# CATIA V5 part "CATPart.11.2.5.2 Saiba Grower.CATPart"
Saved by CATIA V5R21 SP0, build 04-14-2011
Part number: Şaibă Grower (varianta N)
Bounding box of the stored display mesh (mm): x -3.747 to 3.719, y 0 to 1.5, z -3.701 to 3.685
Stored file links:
  C:\Users\MIRCEA\Desktop\MOM\Mogan\model\CATPart.11.2.5.2 Saiba Grower.CATPart
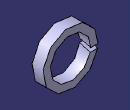
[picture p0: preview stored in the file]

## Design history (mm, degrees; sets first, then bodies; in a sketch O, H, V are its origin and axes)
Parameters
  d1 = 5.5 mm
  d2 = 7.5 mm
  g = 1.5 mm
AxisSystem1: origin (0, 0, 0), X (1, 0, 0), Y (0, 1, 0), Z (0, 0, 1)
Body1 (main body)
  Sketch1 on xy-plane, origin (0, 0, 0), H (1, 0, 0), V (0, 1, 0)
    line L1 (2.75, 1.5) -> (3.75, 1.5)
    line L2 (3.75, 1.5) -> (3.75, 0)
    line L3 (3.75, 0) -> (2.75, 0)
    line L4 (2.75, 0) -> (2.75, 1.5)
    distance L4 V = 2.75 {= d1/2}
    distance L2 V = 3.75 {= d2/2}
    distance L1 L3 = 1.5 {= g}
    horizontal: L1 H, L3 H
    vertical: L2 V, L4 V
  Shaft1: profile Sketch1, axis Sketch1.V, angle 360
  Sketch2 on yz-plane, origin (0, 0, 0), H (0, 1, 0), V (0, 0, 1)
    line L1 (-0.8945, 0.4985) -> (14.3622, -3.5895)
    line L2 (14.3622, -3.5895) -> (14.3622, -4.1072)
    line L3 (14.3622, -4.1072) -> (-0.8945, -0.0191)
    line L4 (-0.8945, -0.0191) -> (-0.8945, 0.4985)
    distance L3 L1 = 0.5 {= g/3}
    distance O L3 = 0.25 {= g/6}
    angle L1 V = 75
    vertical: L2 V, L4 V
  Pocket1: profile Sketch2, direction (-1, 0, 0), through (limit type 3)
